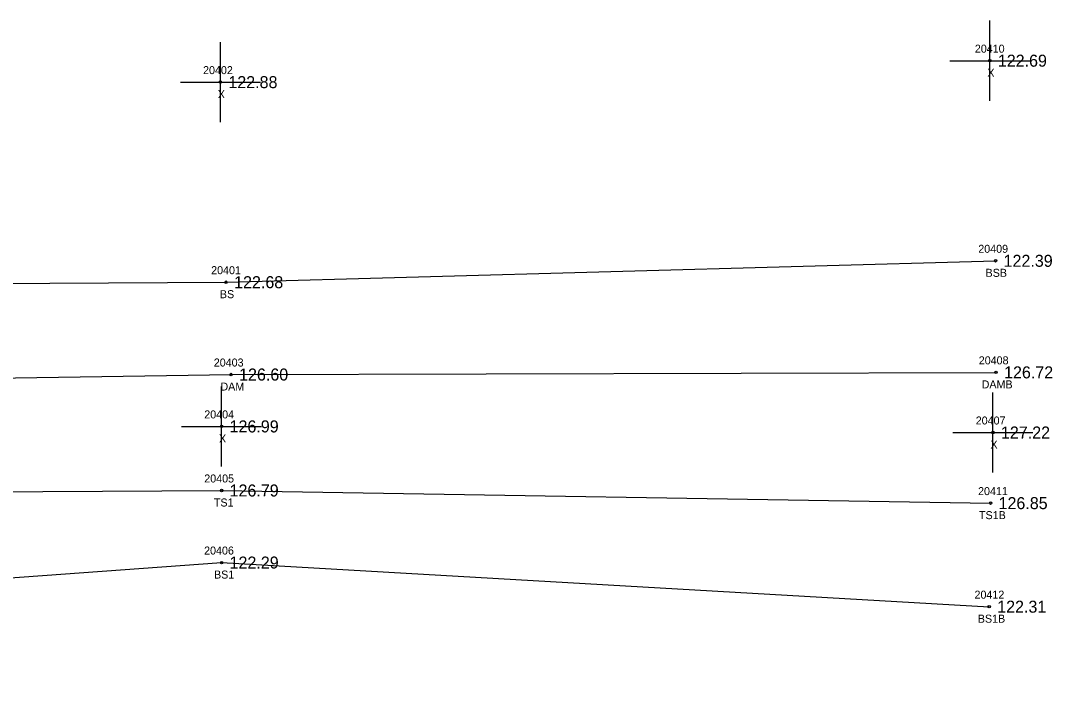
# Model space of a CAD drawing. Extents: x 2375812 to 2377225, y 1024470 to 1025135.
# Drawn here: x 2377080.8 to 2377209.7, y 1025040.9 to 1025123.9 of the extents above; entities that cross this region are included whole.
import ezdxf

# ---------------------------------------------------------------- set-up
doc = ezdxf.new("R2010")
doc.units = 0
for name, color, linetype in [('RD_DTM_BkLn2', 7, 'Continuous'), ('RD_DTM_BkLn_txCode', 7, 'Continuous'), ('RD_EX_Dam', 7, 'Continuous'), ('RD_EX_Dam_txCode', 7, 'Continuous'), ('RD_EX_Misc', 7, 'Continuous'), ('RD_EX_Misc_txCode', 7, 'Continuous'), ('RD_EX_TX_Dam_ELEV', 7, 'Continuous'), ('RD_EX_TX_Misc_ELEV', 7, 'Continuous'), ('RD_SMD_Locator', 7, 'Continuous')]:
    doc.layers.add(name, color=color, linetype=linetype)

msp = doc.modelspace()

# ---------------------------------------------------------------- linework, layer by layer
at = {"layer": 'RD_DTM_BkLn2'}
for points in [[(2376552.99, 1025053.79), (2376560.85, 1025063.21), (2376567.06, 1025075.76), (2376572.77, 1025085.75), (2376582.8, 1025094.03), (2376679.85, 1025092.48), (2376779.73, 1025094.91), (2376887.32, 1025089.81), (2376988.9, 1025090.57), (2377106.48, 1025091.22), (2377202.62, 1025093.89)], [(2376580.3, 1025079.96), (2376576.42, 1025074.43), (2376572.95, 1025066.08), (2376567.78, 1025062.13), (2376680.13, 1025064), (2376781.64, 1025064.6), (2376885.5, 1025064.7), (2376986.85, 1025064.56), (2377105.91, 1025065.21), (2377201.99, 1025063.63)], [(2376554.71, 1025040.88), (2376679.34, 1025046.02), (2376781.14, 1025046.61), (2376885.14, 1025046.71), (2376986.57, 1025047.57), (2377105.91, 1025056.21), (2377201.82, 1025050.7)]]:
    msp.add_lwpolyline(points, dxfattribs=at)
at = {"layer": 'RD_EX_Dam'}
msp.add_lwpolyline([(2376580.3, 1025079.96), (2376679.85, 1025076.24), (2376781.56, 1025078.14), (2376886.41, 1025078.13), (2376988.46, 1025077.85), (2377107.1, 1025079.69), (2377202.68, 1025079.96)], dxfattribs=at)
at = {"layer": 'RD_EX_Misc'}
for p, q in [((2377201.9, 1025113.88), (2377201.9, 1025123.88)), ((2377105.76, 1025111.2), (2377105.76, 1025121.2)), ((2377196.9, 1025118.88), (2377206.9, 1025118.88)), ((2377100.76, 1025116.2), (2377110.76, 1025116.2)), ((2377105.91, 1025068.21), (2377105.91, 1025078.21)), ((2377202.29, 1025067.45), (2377202.29, 1025077.45)), ((2377100.91, 1025073.21), (2377110.91, 1025073.21)), ((2377197.29, 1025072.45), (2377207.29, 1025072.45))]:
    msp.add_line(p, q, dxfattribs=at)
at = {"layer": 'RD_SMD_Locator'}
for centre in [(2377201.9, 1025118.88), (2377105.76, 1025116.2), (2377202.62, 1025093.89), (2377106.48, 1025091.22), (2377107.1, 1025079.69), (2377202.68, 1025079.96), (2377105.91, 1025073.21), (2377202.29, 1025072.45), (2377105.91, 1025065.21), (2377201.99, 1025063.63), (2377105.91, 1025056.21), (2377201.82, 1025050.7)]:
    msp.add_circle(centre, 0.15, dxfattribs=at)

# ---------------------------------------------------------------- texts
at = {"layer": 'RD_DTM_BkLn_txCode'}
for s, p in [('20409', (2377200.46, 1025094.89)), ('20401', (2377104.61, 1025092.22)), ('BSB', (2377201.37, 1025091.89)), ('BS', (2377105.7, 1025089.22)), ('20405', (2377103.75, 1025066.21)), ('20411', (2377200.43, 1025064.63)), ('TS1', (2377104.95, 1025063.21)), ('TS1B', (2377200.55, 1025061.63)), ('20406', (2377103.73, 1025057.21)), ('BS1', (2377104.97, 1025054.21)), ('20412', (2377199.99, 1025051.7)), ('BS1B', (2377200.4, 1025048.7))]:
    msp.add_text(s, height=1, dxfattribs=at).set_placement(p)
at = {"layer": 'RD_EX_Dam_txCode'}
for s, p in [('20408', (2377200.52, 1025080.96)), ('20403', (2377104.94, 1025080.69)), ('DAM', (2377105.77, 1025077.69)), ('DAMB', (2377200.88, 1025077.96))]:
    msp.add_text(s, height=1, dxfattribs=at).set_placement(p)
at = {"layer": 'RD_EX_Misc_txCode'}
for s, p in [('20410', (2377200.03, 1025119.88)), ('20402', (2377103.6, 1025117.2)), ('X', (2377201.59, 1025116.88)), ('X', (2377105.44, 1025114.2)), ('20404', (2377103.75, 1025074.21)), ('20407', (2377200.14, 1025073.45)), ('X', (2377105.59, 1025071.21)), ('X', (2377201.98, 1025070.45))]:
    msp.add_text(s, height=1, dxfattribs=at).set_placement(p)
at = {"layer": 'RD_EX_TX_Dam_ELEV'}
for s, p in [('126.72', (2377203.68, 1025079.21)), ('126.60', (2377108.1, 1025078.94))]:
    msp.add_text(s, height=1.5, dxfattribs=at).set_placement(p)
at = {"layer": 'RD_EX_TX_Misc_ELEV'}
for s, p in [('122.69', (2377202.9, 1025118.13)), ('122.88', (2377106.76, 1025115.45)), ('122.39', (2377203.62, 1025093.14)), ('122.68', (2377107.48, 1025090.47)), ('126.99', (2377106.91, 1025072.46)), ('127.22', (2377203.29, 1025071.7)), ('126.79', (2377106.91, 1025064.46)), ('126.85', (2377202.99, 1025062.88)), ('122.29', (2377106.91, 1025055.46)), ('122.31', (2377202.82, 1025049.95))]:
    msp.add_text(s, height=1.5, dxfattribs=at).set_placement(p)

doc.saveas('drawing.dxf')
